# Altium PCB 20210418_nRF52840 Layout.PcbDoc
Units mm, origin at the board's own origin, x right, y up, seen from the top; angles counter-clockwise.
Board outline 17.42 x 19.45 mm, 4 copper layers (Top Layer, L2_GND, Layer 3, Bottom Layer), stack 1.51 mm thick; 44 components, 56 nets, 250 pads, 364 vias.
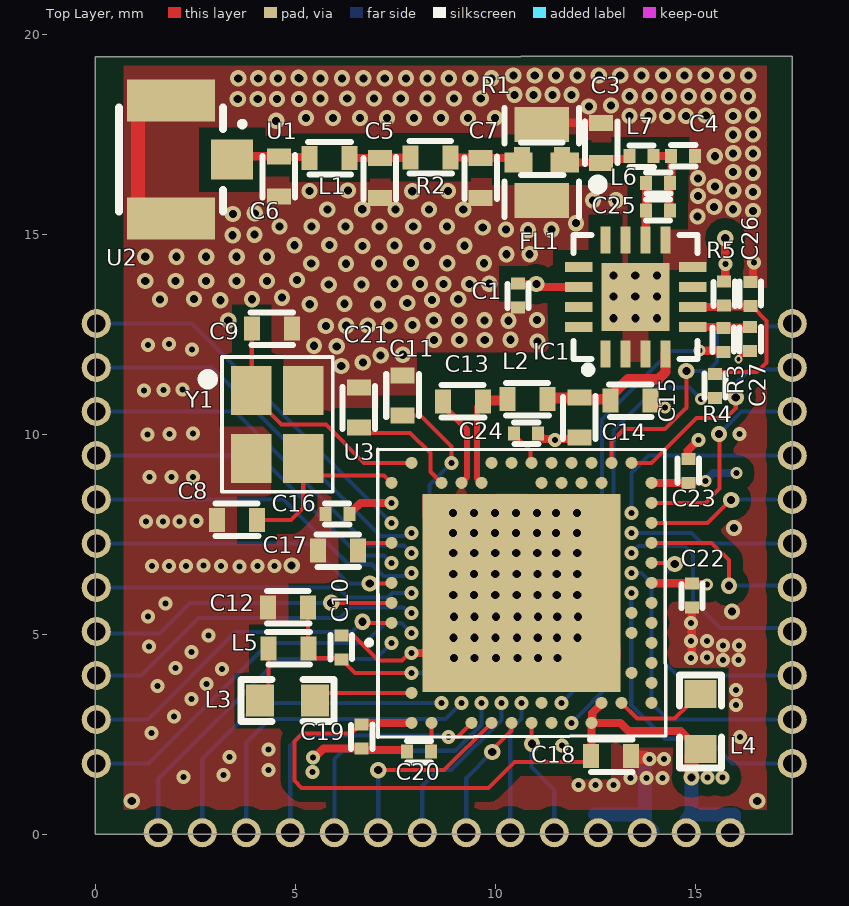
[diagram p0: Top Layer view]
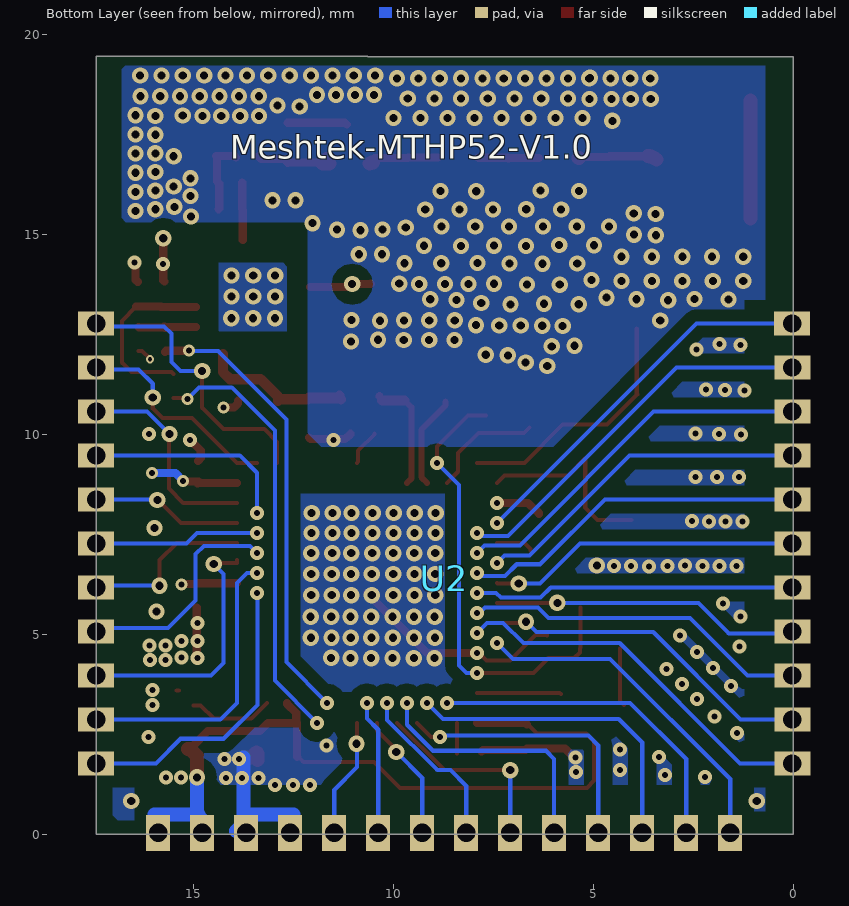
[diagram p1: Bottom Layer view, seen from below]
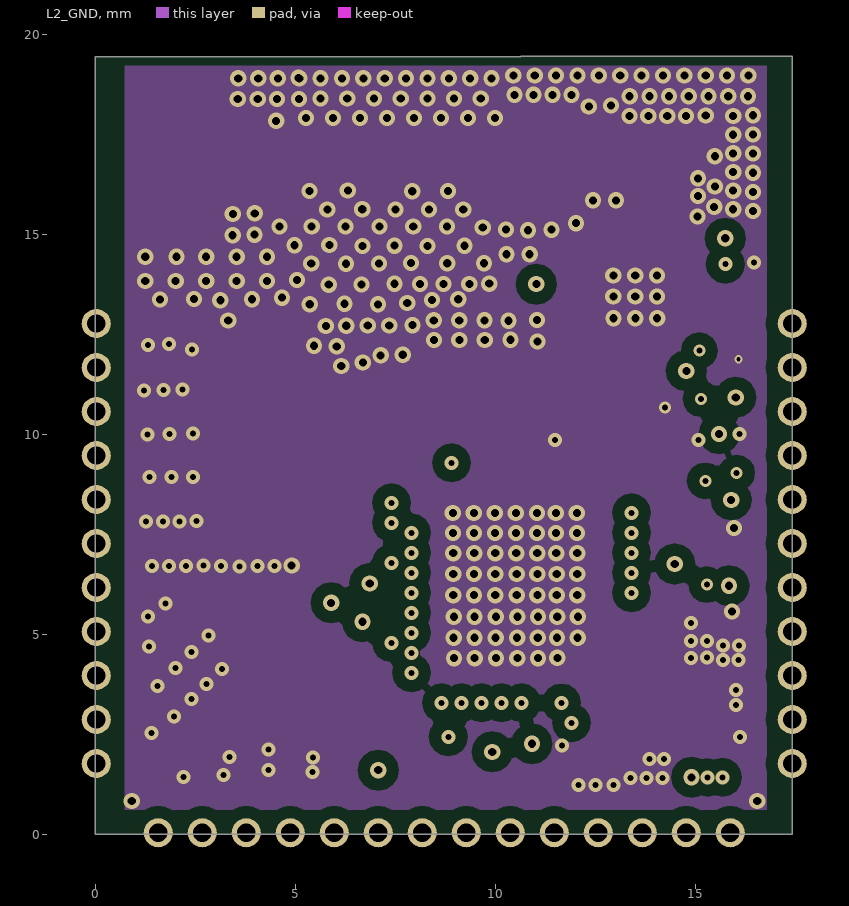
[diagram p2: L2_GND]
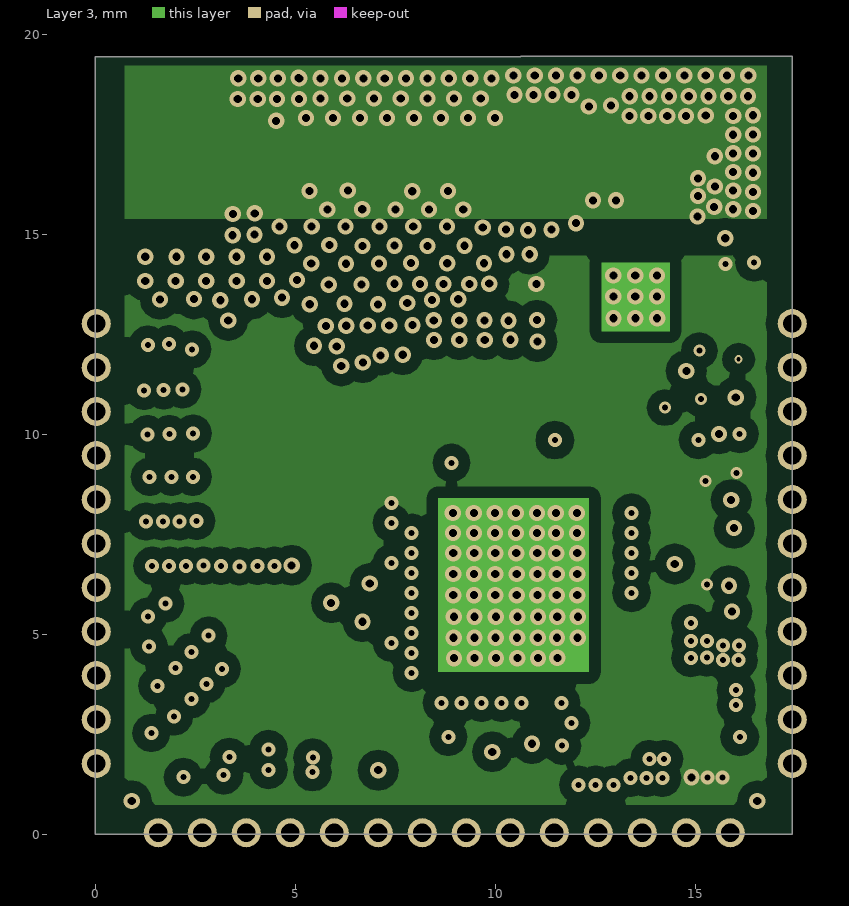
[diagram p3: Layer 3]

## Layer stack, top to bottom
Top Solder: solder mask 0.0102, Solder Resist, Dk 3.5
Top Layer: signal copper 0.0178
Dielectric 1: core 0.286, FR-4, Dk 4.5
L2_GND: signal copper 0.036
Dielectric 2: core 0.83, FR-4, Dk 4.5
Layer 3: signal copper 0.036
Dielectric 3: core 0.286, FR-4, Dk 4.5
Bottom Layer: signal copper 0.0178
Bottom Solder: solder mask 0.0102, Solder Resist, Dk 3.5

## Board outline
10.626,19.44 10.631,19.435 10.645,19.449 17.424,19.449 17.424,0 0,0 0,19.44

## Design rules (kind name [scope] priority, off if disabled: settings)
Clearance [All] p1: gap=0.1 ignorepadtopadclearanceinfootprint=FALSE except(0.3: Arc-Poly Arc-Region Track-Poly Track-Region SMDPad-Poly SMDPad-Region THPad-Poly THPad-Region Via-Poly Via-Region Fill-Poly Fill-Region Poly-Region Poly-Text Poly-Hole Region-Region Region-Text Region-Hole)
PlaneClearance [All] p1: clearance=0.3
PlaneConnect [All] p1: planeconnectstyle=Direct reliefexpansion=0.508 reliefentries=4 reliefconductorwidth=0.254 reliefairgap=0.254
PolygonConnect [All] p1: connectstyle=Direct reliefconductorwidth=0.254 reliefentries=4 polygonreliefangle="90 Angle" airgapwidth=0.254
RoutingVias [All] p1: holewidth=0.203 width=0.406 viastyle="Through Hole" minholewidth=0.203 minwidth=0.406 maxholewidth=0.203 maxwidth=0.406
SolderMaskExpansion [All] p1: expansion=0.102
Width [All] p1: maxlimit=0.35 minlimit=0.102 preferedwidth=0.203
28 further rules are at their usual default settings.

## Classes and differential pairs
component class "20210418_Controller Section": C8 C9 C10 C11 C12 C13 C14 C15 C16 C17 C18 C19 C20 C21 C22 C23 C24 L2 L3 L4 L5 U2 U3 Y1
component class "Antenna Section": C1 C3 C4 C5 C6 C7 C25 C26 C27 FL1 IC1 L1 L6 L7 R1 R2 R3 R4 R5 U1

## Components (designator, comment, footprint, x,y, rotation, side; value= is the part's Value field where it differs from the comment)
C1 "1uF" C0201 10.59,13.46 r90 top
C3 "DNP" C0402 12.653,17.324 r90 top
C4 "1.3pF" C0201 14.698,16.983 r180 top
C5 "1.2pF" C0402 7.104,16.361 r270 top
C6 "1.2pF" C0402 4.575,16.409 r270 top
C7 "DNP" C0402 9.62,16.367 r270 top
C8 "12pF" C0402 3.5,7.868 r180 top
C9 "12pF" C0402 4.449,12.631 r0 top
C10 "1uF" C0201 6.119,4.673 r270 top
C11 "DNP" C0402 7.689,11.009 r90 top
C12 "47nF" C0402 4.781,5.682 r180 top
C13 "0.8pF" C0402 9.148,10.829 r180 top
C14 "0.5pF" C0402 12.089,10.375 r270 top
C15 "DNP" C0402 13.415,10.823 r0 top
C16 "100nF" C0201 6.048,7.979 r0 top
C17 "DNP" C0402 6.105,7.078 r0 top
C18 "4.7uF" C0402 12.935,1.945 r0 top
C19 "1uF" C0201 6.681,2.441 r90 top
C20 "100nF" C0201 8.091,2.04 r0 top
C21 "100pF" C0402 6.58,10.627 r270 top
C22 "100nF" C0201 14.94,5.963 r90 top
C23 "100nF" C0201 14.801,9.083 r270 top
C24 "820pF" C0201 10.77,10.048 r180 top
C25 "0.7pF" C0201 14.066,15.628 r180 top
C26 "DNP" C0201 16.347,13.512 r270 top
C27 "DNP" C0201 16.399,12.378 r90 top
FL1 "LFB212G45CG1B982" FILT-BPF4_2X1P25 11.159,16.794 r270 top
IC1 "RFX2401C" QFN16_0P5_3X3_EP_0P6 13.505,13.43 r90 top
L1 "8.2nH" L0402 5.876,16.908 r0 top
L2 "4.7nH" L0402 10.784,10.874 r180 top
L3 "10uH" L0603 4.786,3.307 r180 top
L4 "10uH" L0603 15.097,2.838 r90 top
L5 "15nH" L0402 4.851,4.649 r0 top
L6 "1.2nH" L0201 14.056,16.277 r180 top
L7 "0.7nH" L0201 13.669,16.951 r0 top
R1 "DNP" R0402 11.185,16.898 r180 top
R2 "0E" R0402 8.392,16.938 r180 top
R3 "1K" R0201#1 15.775,12.442 r270 top
R4 "1K" R0201#1 15.565,11.294 r270 top
R5 "10K, DNP" R0201#2 15.775,13.431 r90 top
U1 "Component_1" "UFL Conn" 2.022,16.865 r90 top
U2 "nRF52840 Module" "nRF52840 Module" 9.764,13.875 r0 top locked
U3 "nRF52840" nRF52840 10.781,4.637 r90 top
Y1 "XRCGB32M000FXH2CR0" XTAL4_1P3_2P5X2_0P55 4.548,10.245 r270 top

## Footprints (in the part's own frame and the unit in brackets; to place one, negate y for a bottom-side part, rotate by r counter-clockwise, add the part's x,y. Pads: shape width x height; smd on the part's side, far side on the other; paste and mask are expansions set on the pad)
C0201 [mm] "C0201, CAP"
  rect 0.3x0.35 smd mask+0.051: 1(0.302,0.03) 2(-0.298,0.03)
  silkscreen extent -0.31,-0.24 0.3,0.29, body extent -0.3,-0.12 0.3,0.18, height 0.5
C0402 [mm] "C0402"
  rect 0.4x0.6 smd mask+0.051: 1(-0.539,0.013) 2(0.461,0.013)
  silkscreen extent -0.57,-0.4 0.49,0.42, body extent -0.56,-0.26 0.49,0.29, height 1
FILT-BPF4_2X1P25 [mil] "FILT-BPF4_2X1P25"
  rect 20x27.99 smd mask+2: 1(0.06,22.87) 3(0.06,-22.87)
  rect 34.02x54.02 smd mask+2: 2(37.46,0) 4(-37.34,0)
  silkscreen extent -54,-37 54,37, body extent -42,-27 42,27, height 0
L0201 [mm] "L0201, INDUCTOR"
  rect 0.3x0.35 smd mask+0.051: 1(0.29,0.001) 2(-0.31,0.001)
  silkscreen extent -0.32,-0.27 0.29,0.26, body extent -0.31,-0.15 0.29,0.15, height 0.5
L0402 [mm] "L0402, INDUCTOR"
  rect 0.4x0.6 smd mask+0.051: 1(-0.518,-0.002) 2(0.482,-0.002)
  silkscreen extent -0.55,-0.41 0.51,0.4, body extent -0.54,-0.28 0.51,0.27, height 1
L0603 [mm] "L0603_INDUCTOR"
  rect 0.7x0.8 smd mask+0.051: 1(-0.708,-0.033) 2(0.667,-0.033)
  silkscreen extent -1.18,-0.56 1.14,0.49
nRF52840 [mm] "nRF52840_SOC_Footprint"
  round 0.3 smd: A8(0.147,3.377) A10(0.647,3.377) A12(1.147,3.377) A14(1.647,3.377) A16(2.147,3.377) A18(2.647,3.377) A20(3.147,3.377) A22(3.647,3.377) A23(4.147,3.377) AA24(4.647,-2.123) AB2(-1.353,-2.373) AC5(-0.603,-2.623) AC9(0.397,-2.623) AC11(0.897,-2.623) AC13(1.397,-2.623) AC15(1.897,-2.623) AC17(2.397,-2.623) AC19(2.897,-2.623) AC21(3.397,-2.623) AC24(4.647,-2.623) AD2(-1.353,-3.123) AD4(-0.853,-3.123) AD6(-0.353,-3.123) AD8(0.147,-3.123) AD10(0.647,-3.123) AD12(1.147,-3.123) AD14(1.647,-3.123) AD16(2.147,-3.123) AD18(2.647,-3.123) AD20(3.147,-3.123) AD22(3.647,-3.123) AD23(4.147,-3.123) B1(-1.853,2.877) B3(-1.103,2.877) B5(-0.603,2.877) B7(-0.103,2.877) B9(0.397,2.877) B11(0.897,2.877) B13(1.397,2.877) B15(1.897,2.877) B17(2.397,2.877) B19(2.897,2.877) B24(4.647,2.877) C1(-1.853,2.377) D2(-1.353,2.127) D23(4.147,2.127) E24(4.647,1.877) F2(-1.353,1.627) F23(4.147,1.627) G1(-1.853,1.377) H2(-1.353,1.127) H23(4.147,1.127) J1(-1.853,0.877) J24(4.647,0.877) K2(-1.353,0.627) L1(-1.853,0.377) L24(4.647,0.377) M2(-1.353,0.127) N1(-1.853,-0.123) N24(4.647,-0.123) P2(-1.353,-0.373) P23(4.147,-0.373) R1(-1.853,-0.623) R24(4.647,-0.623) T2(-1.353,-0.873) T23(4.147,-0.873) U1(-1.853,-1.123) U24(4.647,-1.123) V23(4.147,-1.373) W1(-1.853,-1.623) W24(4.647,-1.623) Y2(-1.353,-1.873) Y23(4.147,-1.873)
  rect 4.95x4.95 smd: DP1(1.397,0.127)
  silkscreen extent -2.21,-3.48 4.99,3.96
"nRF52840 Module" [mil] "nRF52840 Module_PCB"
  round 28.62 / inner round 28.62 / far side rect 0x0 hole 18 mask+2: 1(-383.5,-43.66) 2(-383.5,-86.97) 3(-383.5,-130.27) 4(-383.5,-173.58) 5(-383.5,-216.89) 6(-383.5,-260.19) 7(-383.5,-303.5) 8(-383.5,-346.81) 9(-383.5,-390.12) 10(-383.5,-433.42) 11(-383.5,-476.73) 13(-279.19,-544.84) 14(-235.88,-544.84) 15(-192.57,-544.84) 16(-149.27,-544.84) 17(-105.96,-544.84) 18(-62.65,-544.84) 19(-19.35,-544.84) 20(23.96,-544.84) 21(67.27,-544.84) 22(110.57,-544.84) 23(153.88,-544.84) 24(197.19,-544.84) 25(240.5,-544.84) 26(301.5,-476.72) 27(301.5,-433.41) 28(301.5,-390.11) 29(301.5,-346.8) 30(301.5,-303.49) 31(301.5,-260.18) 32(301.5,-216.88) 33(301.5,-173.57) 34(301.5,-130.26) 35(301.5,-86.96) 36(301.5,-43.65)
  round 28.62 / inner round 28.62 / far side round 0 hole 18 mask+2: 12(-322.5,-544.84)
  rect 35.44x23.62 smd far side paste+0 mask+2: ""(-383.54,-476.73) ""(-383.54,-433.43) ""(-383.54,-390.12) ""(-383.54,-346.81) ""(-383.54,-303.51) ""(-383.54,-260.2) ""(-383.54,-216.89) ""(-383.54,-173.58) ""(-383.54,-130.28) ""(-383.54,-86.97) ""(-383.52,-43.66) ""(301.52,-476.73) ""(301.52,-433.43) ""(301.52,-390.12) ""(301.52,-346.81) ""(301.52,-303.5) ""(301.52,-260.2) ""(301.52,-216.89) ""(301.52,-173.58) ""(301.52,-130.28) ""(301.52,-86.97) ""(301.52,-43.66)
  rect 23.62x35.44 smd far side paste+0 mask+2: ""(-322.49,-544.85) ""(-279.19,-544.85) ""(-235.88,-544.85) ""(-192.57,-544.85) ""(-149.26,-544.85) ""(-105.96,-544.85) ""(-62.65,-544.85) ""(-19.34,-544.85) ""(23.96,-544.85) ""(67.27,-544.85) ""(110.58,-544.85) ""(153.88,-544.84) ""(197.18,-544.84) ""(240.49,-544.84)
  body extent -383,-545 301,258, height 0
QFN16_0P5_3X3_EP_0P6 [mil] "QFN16_0P5_3X3_EP_0P6"
  rect 27x10 smd mask+2: 1(-56.1,29.53) 2(-56.1,9.84) 3(-56.1,-9.84) 4(-56.1,-29.53) 9(56.1,-29.53) 10(56.1,-9.84) 11(56.1,9.84) 12(56.1,29.53)
  rect 10x27 smd mask+2: 5(-29.53,-56.1) 6(-9.84,-56.1) 7(9.84,-56.1) 8(29.53,-56.1) 13(29.53,56.1) 14(9.84,56.1) 15(-9.84,56.1) 16(-29.53,56.1)
  rect 67.01x67.01 smd paste-33.5 mask+2: 17(0,0)
  silkscreen extent -61,-61 61,61, body extent -61,-61 61,61, height 0
R0201#1 [mm] "0201, Res"
  rect 0.3x0.35 smd mask+0.051: 1(0.385,-0.07) 2(-0.215,-0.07)
  silkscreen extent -0.22,-0.34 0.39,0.19, body extent -0.21,-0.22 0.38,0.08, height 0.5
R0201#2 [mm] "0201, Res"
  rect 0.3x0.35 smd mask+0.051: 1(0.385,0.057) 2(-0.215,0.057)
  silkscreen extent -0.22,-0.22 0.39,0.32, body extent -0.21,-0.09 0.38,0.21, height 0.5
R0402 [mm]
  rect 0.4x0.6 smd mask+0.051: 1(-0.487,0.018) 2(0.513,0.018)
  silkscreen extent -0.52,-0.39 0.54,0.42, body extent -0.51,-0.26 0.54,0.29, height 1
"UFL Conn" [mm] "UFL Connector"
  rect 1x1.05 smd: 1(0,-1.398)
  rect 1.05x2.2 smd: 2(-1.475,0.127) 3(1.475,0.127)
  silkscreen extent -1.3,-1.68 1.3,1.43
XTAL4_1P3_2P5X2_0P55 [mm] "XTAL4_1P3_2P5X2_0P55"
  rect 1.219x1.016 smd mask+0.051: 1(-0.85,-0.65) 2(0.85,-0.65) 3(0.85,0.65) 4(-0.85,0.65)
  silkscreen extent -1.68,-1.86 1.68,1.38, body extent -1.3,-1.05 1.3,1.05, height 0

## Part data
C1 C4 C10 C16 C19 C20 C22 C23 C24 C25 C26 C27: library part C0201, "C0201, CAP"
C3 C5 C7 C8 C9 C11 C13 C17 C18 C21: library part C0402, "C0402"
C6: library part C0402, "1.2pFC0402"
C12: library part C0402, "Capacitor, X7R, ±10 %"
C14 C15: library part C0402, "Capacitor, NP0, ±10 %, 0402"
FL1: library part LFB212G45CG1C187, "Filter", Manufacturer_Name="Murata Electronics", Mouser Part Number=81-LFB212G45CG1C187
IC1: "Integrated Circuit", Manufacturer_Name=Skyworks, Mouser Part Number=477-RFX2401C
L1: library part L0402, "8.2nH, 0402"
L2: library part L0402, "High frequency chip inductor ±5 %"
L3 L4: library part L0603, "L0603, INDUCTOR"
L5: library part L0402
L6 L7: library part L0201, "L0201, INDUCTOR"
R1: library part R0402
R2: library part R0402, "0402"
R3 R4 R5: library part R0201, "R0201"
U2: "nRF52840 Module_Symbole"
U3: "nRF52840 SOC"
Y1: "Crystal or Oscillator", Manufacturer_Name="Murata Electronics", Mouser Part Number=81-XRCGB32M000FXH2CR

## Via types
v1: diameter 0.406, hole 0.203, Top Layer to Bottom Layer, tented both sides, 260 vias
v2: diameter 0.35, hole 0.15, Top Layer to Bottom Layer, tented both sides, 97 vias
v3: diameter 0.3, hole 0.15, Top Layer to Bottom Layer, tented both sides, 6 vias
v4: diameter 0.204, hole 0.102, Top Layer to Bottom Layer, tented both sides, 1 vias

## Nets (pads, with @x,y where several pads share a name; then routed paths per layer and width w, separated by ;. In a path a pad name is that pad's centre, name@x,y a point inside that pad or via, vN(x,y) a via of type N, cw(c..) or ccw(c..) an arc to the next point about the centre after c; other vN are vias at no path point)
ANT: C13.1 L2.2 U3.H23 | length 2.8
  Top Layer w0.15: U3.H23 9.547,8.891 9.547,10.676 C13.1
  Top Layer w0.203: C13.1 C13.1@9.717,10.846 ; L2.2@10.272,10.846 L2.2 ; L2.2@10.339,10.94 L2.2@10.339,10.96
  Top Layer w0.254: C13.1@9.717,10.846 L2.2@10.272,10.846
BT_TXRX: C14.1 C15.1 IC1.4 L2.1 | length 4.6
  Top Layer w0.254: L2.1 11.321,10.895 12.083,10.895 C14.1 ; L2.1@11.339,10.96 11.339,10.956 11.381,10.914 C14.1 ; C15.1 C15.1@12.876,10.864 ; IC1.4 14.255,11.552 14.076,11.373 13.313,11.373 12.876,10.936 C15.1@12.876,10.864 ; C14.1 12.141,10.875 12.837,10.875 12.851,10.889 C15.1@12.876,10.864
DCC: L3.1 U3.B3 | length 2.1
  Top Layer w0.102: L3.1@5.804,3.501 5.836,3.534 U3.B3
DEC1: C20.1 U3.C1 | length 0.8
  Top Layer w0.102: C20.1@8.399,2.018 8.401,2.02 8.401,2.781 U3.C1
DEC2: C17.2 U3.A18 | length 0.9
  Top Layer w0.102: C17.2 6.566,7.135 6.715,7.284 U3.A18
DEC3: C21.2 U3.D23 | length 2.9
  Top Layer w0.102: C21.2 6.727,10.032 7.87,10.032 8.377,9.525 8.377,9.061 U3.D23
DEC4_6: C10.1 C11.1 C12.1 L5.2 U3.B5 U3.E24 | length 11.7
  Top Layer w0.102: C12.1 5.32,4.661 L5.2 5.333,4.547 5.482,4.398 6.122,4.398 C10.1 6.486,4.034 v2(7.904,4.034) ; C11.1 8.13,10.47 8.904,9.696 v2(8.904,9.284)
  Bottom Layer w0.102: v2(7.904,4.034) 8.166,4.034 8.348,4.216 8.348,8.728 v2(8.904,9.284)
DEC5: C24.1 U3.N24 | length 0.9
  Top Layer w0.102: C24.1 10.468,9.993 10.874,9.587 10.874,9.314 U3.N24
GND: C1.2 C3.2 C4.2 C5.2 C6.2 C7.2 C8.2 C9.2 C11.2 C12.2 C13.2 C14.2 C15.2 C16.2 C17.1 C18.2 C19.2 C20.2 C21.1 C22.2 C23.2 C24.2 C26.2 C27.2 FL1.2 FL1.4 IC1.2 IC1.3 IC1.8 IC1.9 IC1.11 IC1.17 U1.2 U1.3 U2.22 U2.23 U3.B7 U3.DP1 U3.F23 Y1.2 Y1.4 | length 23.3
  Top Layer w0.102: 6.149,4.971 6.157,4.979 6.443,4.979 7.076,4.346 7.664,4.346 7.852,4.534 U3.B7 ; v4(16.082,11.873) 16.082,11.888 16.274,12.08 C27.2
  Top Layer w0.15: C13.2 8.687,10.723 9.297,10.112 9.297,8.927 U3.F23
  Top Layer w0.203: v2(5.435,1.916) 5.475,1.916 5.699,2.141 6.649,2.141 C19.2 6.688,2.106 7.756,2.106 C20.2 ; U3.B7 9.154,4.534 U3.DP1 ; C24.2 11.068,9.993 11.117,9.945 11.142,9.945 11.206,9.88 11.46,9.88 v2(11.488,9.852) 11.516,9.88 12.069,9.88 C14.2 ; FL1.4 11.201,17.785 C3.2 ; C15.2 13.876,10.764 13.975,10.666 v3@14.24,10.666 ; C23.2@14.879,9.333 C23.2 14.811,9.401 14.811,9.591 v2(15.075,9.855) ; v2@14.91,4.404 C22.2 ; C26.2 16.392,13.81 16.441,13.859 16.441,14.264 v2(16.469,14.292)
  Top Layer w0.35: U1.2@1.068,15.39 U1.3@1.068,18.34 ; C18.2@13.396,1.858 C18.2 13.396,2.023 13.421,2.048 13.556,1.914 v2@13.745,1.914
  Bottom Layer w0.15: 12.493,0.498 12.493,0.115 U2.22
  Bottom Layer w0.35: 12.493,0.498 13.594,0.498 ; v2@13.745,1.914 13.745,0.273 13.934,0.084
  other v1: 0.909,0.833 16.548,0.831 8.963,4.401 9.482,4.401 10.013,4.401 10.55,4.401 11.064,4.401 11.549,4.409 8.958,4.911 9.477,4.911 10.008,4.911 10.545,4.911 11.059,4.911 11.544,4.911 12.058,4.911 8.962,5.437 9.481,5.437 10.012,5.437 10.549,5.437 11.063,5.437 11.548,5.437 12.062,5.437 15.915,5.568 8.948,5.976 9.467,5.976 9.998,5.976 10.535,5.976 11.049,5.976 11.534,5.976 12.048,5.976 8.948,6.505 9.467,6.505 9.998,6.505 10.535,6.505 11.049,6.505 11.534,6.505 12.048,6.505 4.908,6.72 8.947,7.026 9.472,7.026 9.998,7.026 10.523,7.026 11.048,7.026 11.522,7.026 12.047,7.026 8.94,7.533 9.465,7.533 9.991,7.533 10.516,7.533 11.041,7.533 11.515,7.533 12.04,7.533 15.968,7.652 8.937,8.033 9.462,8.033 9.988,8.033 10.513,8.033 11.038,8.033 11.512,8.033 12.037,8.033 6.146,11.705 6.687,11.79 7.133,11.971 7.685,11.987 5.467,12.21 6.036,12.196 11.051,12.315 8.465,12.358 9.1,12.358 9.735,12.358 10.381,12.362 5.762,12.705 6.273,12.71 6.811,12.715 7.348,12.715 7.928,12.726 3.321,12.842 10.326,12.836 8.461,12.846 9.096,12.846 9.731,12.846 11.041,12.854 12.953,12.898 13.499,12.898 14.045,12.898 5.359,13.249 7.068,13.246 6.228,13.262 7.797,13.278 3.124,13.35 8.416,13.352 8.416,13.352 1.614,13.369 3.918,13.373 9.072,13.374 9.072,13.374 2.466,13.379 4.668,13.413 12.95,13.443 13.496,13.443 14.042,13.443 5.836,13.739 6.651,13.741 8.117,13.753 8.704,13.753 9.35,13.758 7.48,13.761 9.846,13.763 1.246,13.833 2.008,13.833 2.77,13.833 3.532,13.833 4.294,13.833 5.038,13.852 12.95,13.965 13.496,13.965 14.042,13.965 5.398,14.265 6.265,14.26 7.092,14.266 7.892,14.279 8.796,14.273 9.713,14.273 1.246,14.437 2.028,14.437 2.77,14.437 3.532,14.437 4.294,14.437 10.278,14.5 10.857,14.5 4.979,14.723 6.679,14.706 7.481,14.713 8.305,14.706 9.226,14.712 5.849,14.728 3.432,14.973 3.981,14.989 10.816,15.1 10.264,15.12 11.402,15.114 9.685,15.168 4.606,15.192 5.408,15.19 6.254,15.19 7.101,15.19 7.947,15.19 8.794,15.19 12.013,15.276 15.055,15.443 3.437,15.506 3.986,15.522 16.442,15.578 5.799,15.616 6.672,15.632 6.672,15.616 7.501,15.616 8.339,15.616 9.197,15.616 15.945,15.623 15.47,15.684 12.442,15.846 13.019,15.846 15.066,15.954 16.442,16.057 5.353,16.081 6.312,16.092 7.922,16.074 8.813,16.083 15.945,16.089 15.487,16.19 15.066,16.397 16.442,16.536 15.945,16.555 15.487,16.948 15.945,17.021 16.442,17.015 15.945,17.487 16.442,17.494 4.52,17.834 5.264,17.904 5.939,17.904 6.614,17.904 7.289,17.904 7.963,17.904 8.638,17.904 9.313,17.904 9.988,17.904 13.352,17.958 13.824,17.958 14.297,17.958 14.769,17.958 15.26,17.969 15.945,17.953 16.442,17.973 12.337,18.193 12.889,18.215 3.561,18.381 4.059,18.381 4.539,18.381 5.089,18.381 5.631,18.391 6.298,18.391 6.966,18.391 7.633,18.391 8.301,18.391 8.968,18.391 9.636,18.391 13.358,18.449 13.851,18.449 14.343,18.449 14.836,18.449 15.329,18.449 15.821,18.449 16.314,18.449 10.478,18.484 10.953,18.484 11.429,18.484 11.904,18.484 3.571,18.897 4.072,18.897 4.562,18.897 5.078,18.909 5.096,18.897 5.631,18.897 6.165,18.897 6.699,18.897 7.233,18.897 7.768,18.897 8.302,18.897 8.836,18.897 9.371,18.897 9.905,18.897 16.324,18.966 10.45,18.967 10.984,18.967 11.519,18.967 12.053,18.967 12.587,18.967 13.122,18.967 13.656,18.967 14.19,18.967 14.724,18.967 15.259,18.967 15.793,18.967
  other v2: 12.073,1.236 12.509,1.235 12.948,1.235 13.372,1.41 13.775,1.407 14.176,1.407 2.199,1.424 3.209,1.475 5.427,1.552 4.328,1.61 13.85,1.882 14.221,1.882 3.349,1.925 4.328,2.122 11.671,2.213 16.111,2.431 1.4,2.528 1.969,2.943 16.02,3.236 2.4,3.374 16.016,3.601 1.548,3.71 2.779,3.752 3.168,4.131 2,4.152 15.693,4.351 16.075,4.351 14.885,4.404 15.285,4.417 7.901,4.527 2.4,4.552 1.341,4.69 15.693,4.713 16.091,4.713 14.885,4.829 15.288,4.833 2.831,4.962 14.885,5.28 1.321,5.443 1.756,5.767 3.602,6.696 1.422,6.711 1.845,6.711 2.269,6.711 2.702,6.714 3.138,6.711 4.054,6.705 4.477,6.711 1.685,7.815 1.267,7.819 2.104,7.821 2.53,7.831 1.358,8.935 1.904,8.935 2.435,8.935 1.305,9.996 1.851,10.004 2.442,10.019 16.106,10.008 1.218,11.089 1.708,11.101 2.177,11.122 2.42,12.12 1.312,12.234 1.843,12.249
  other v3: 14.241,10.665
NetC3_1: C3.1 FL1.1 L7.2 R1.1 | length 2
  Top Layer w0.203: FL1.1 11.744,16.789 12.636,16.789 C3.1@12.638,16.787 ; C3.1 C3.1@12.638,16.787 ; L7.2 13.359,16.927 13.31,16.878 12.73,16.878 C3.1@12.638,16.787
  Top Layer w0.35: FL1.1@11.587,16.763 FL1.1@11.767,16.763 ; R1.1 11.672,16.789 FL1.1@11.697,16.764 ; FL1.1@11.767,16.781 11.774,16.788 FL1.1@11.776,16.785
NetC4_1: C4.1 C25.2 L6.2 L7.1 | length 1.9
  Top Layer w0.203: L7.1@13.926,16.919 L7.1 C4.1@14.395,16.953 ; C25.2@14.364,15.622 14.348,15.638 14.348,16.264 14.404,16.32 C4.1@14.404,16.913 ; C4.1@14.389,16.898 C4.1@14.404,16.913 ; C4.1@14.427,16.956 14.404,16.933 C4.1@14.404,16.913
NetC5_1: C5.1 L1.2 R2.2 | length 1.5
  Top Layer w0.203: L1.2 6.362,16.903 7.114,16.903 C5.1 7.127,16.91 7.869,16.91 R2.2
NetC6_1: C6.1 L1.1 U1.1 | length 2.2
  Top Layer w0.203: U1.1 3.503,16.948 3.591,16.948 C6.1 4.609,16.927 5.337,16.927 5.355,16.909 L1.1
  Top Layer w0.35: U1.1 cw(c3.625,16.66) 3.591,16.948 cw(c3.625,16.66) U1.1@3.625,16.95 ; L1.1@5.355,16.909 L1.1@5.369,16.909
NetC7_1: C7.1 FL1.3 R1.2 R2.1 | length 1.7
  Top Layer w0.203: R2.1 8.886,16.913 9.626,16.913 C7.1 FL1.3@10.465,16.906
  Top Layer w0.35: FL1.3@10.502,16.798 cw(c10.502,16.678) FL1.3@10.587,16.763
NetC25_1: C25.1 IC1.10 L6.1 | length 2.1
  Top Layer w0.203: IC1.10 13.76,14.86 13.76,15.594 C25.1 C25.1 C25.1@13.765,15.623 ; L6.1 13.765,16.275 C25.1@13.765,15.623 ; L6.1@13.78,16.296 13.772,16.288 13.772,15.63 C25.1@13.765,15.623
NetC26_1: C26.1 IC1.6 R4.2 R5.2 | length 4.5
  Top Layer w0.102: R4.2 15.538,11.553 16.543,11.553 16.777,11.787 16.777,12.835 16.424,13.188 16.402,13.21 C26.1
  Top Layer w0.203: IC1.6 15.784,13.18 ccw(c15.784,13.214) 15.807,13.19 15.809,13.188 C26.1@16.424,13.188
NetC27_1: C27.1 IC1.5 R3.2 | length 1.5
  Top Layer w0.203: IC1.5 15.686,12.68 ccw(c15.686,12.739) R3.2@15.728,12.697 ; R3.2 15.716,12.668 16.358,12.668 C27.1
NetL3_2: L3.2 L5.1 | length 1.5
  Top Layer w0.102: L3.2@4.233,3.229 4.333,3.33 L5.1
NetL4_2: L4.2 U3.AB2 | length 2.2
  Top Layer w0.102: U3.AB2 13.547,2.891 14.484,2.891 14.815,3.222 L4.2@14.991,3.222 ; L4.2@15.359,3.59 L4.2@15.409,3.59
P0.00/XL1: U2.13 U3.D2 | length 8.4
  Bottom Layer w0.102: U2.13 2.673,1.882 4.075,3.284 v2(8.654,3.284)
P0.01/XL2: U2.14 U3.F2 | length 8.1
  Bottom Layer w0.102: U2.14 3.773,2.296 4.36,2.883 8.753,2.883 v2(9.154,3.284)
P0.02/AIN0: U2.8 U3.A12 | length 7.7
  Top Layer w0.102: v1(5.895,5.784) U3.A12
  Bottom Layer w0.102: U2.8 0.066,5.022 1.609,5.022 2.371,5.784 v1(5.895,5.784)
P0.03/AIN1: U2.7 U3.B13 | length 8
  Bottom Layer w0.102: U2.7 6.06,6.166 6.312,5.914 7.306,5.914 7.426,6.034 v2(7.904,6.034)
P0.04/AIN2: U2.17 U3.J1 | length 4.9
  Top Layer w0.102: v1(7.073,1.601) 8.721,1.601 U3.J1
  Bottom Layer w0.102: U2.17 v1(7.073,1.601)
P0.05/AIN3: U2.18 U3.K2 | length 4.3
  Bottom Layer w0.102: U2.18 8.173,1.21 8.564,1.601 8.897,1.601 10.154,2.858 v2(10.154,3.284)
P0.06: U2.19 U3.L1 | length 3.2
  Top Layer w0.102: v1(9.921,2.057) 9.921,2.104 10.404,2.587 U3.L1
  Bottom Layer w0.102: 9.273,0.036 9.273,1.408 v1(9.921,2.057)
P0.07: U2.20 U3.M2 | length 3.4
  Bottom Layer w0.102: U2.20 10.373,2.612 10.654,2.893 v2(10.654,3.284)
P0.08: U2.21 U3.N1 | length 3
  Top Layer w0.102: U3.N1 10.904,2.271 v1(10.913,2.262)
  Bottom Layer w0.102: v1(10.913,2.262) 10.913,2.256 10.902,2.245 10.902,1.678 11.473,1.107 U2.21
P0.18/RESET/QSPI_CSN: U2.26 U2.@17.423,1.766 U3.AC13 | length 7.4
  Bottom Layer w0.102: v2(13.404,6.034) 13.396,6.026 13.396,3.235 14.245,2.386 15.312,2.386 15.932,1.766 U2.26
P0.19/QSPI/SCK: U2.27 U3.AC15 | length 7.3
  Bottom Layer w0.102: v2(13.404,6.534) 13.654,6.534 13.904,6.284 13.904,3.284 14.322,2.866 U2.27
P0.20: U2.28 U2.@17.423,3.966 U3.AD16 | length 6.6
  Top Layer w0.102: U3.AD16@13.904,6.854 U3.AD16 13.905,6.783 14.457,6.783 v1(14.485,6.755)
  Bottom Layer w0.102: v1(14.485,6.755) 14.237,6.507 14.237,4.284 14.555,3.966 U2.28
P0.21/QSPI: U2.29 U2.@17.423,5.066 U3.AC17 | length 5.7
  Bottom Layer w0.102: v2(13.404,7.034) 13.58,7.21 14.731,7.21 14.94,7.001 14.94,5.841 15.63,5.151 17.215,5.151 17.276,5.212 U2.29
P0.22/QSPI: U2.30 U3.AD18 | length 4.4
  Top Layer w0.102: U3.AD18 15.409,7.284 15.841,6.852 v1(15.841,6.213)
  Bottom Layer w0.102: v1(15.841,6.213) 17.371,6.213 17.42,6.164 U2.30 17.421,6.168
P0.23/QSPI: U2.31 U2.@17.423,7.266 U3.AC19 | length 4.1
  Bottom Layer w0.102: v2(13.404,7.534) 14.901,7.534 15.169,7.266 U2.31
P0.24: U2.32 U3.AD20 | length 3.8
  Top Layer w0.102: U3.AD20 15.304,7.784 15.901,8.381 15.901,8.363 v1(15.895,8.357)
  Bottom Layer w0.102: v1(15.895,8.357) 15.904,8.366 U2.32
P0.25: U2.33 U3.AC21 | length 5.2
  Bottom Layer w0.102: v2(13.404,8.034) 13.404,9.036 13.834,9.466 U2.33
P0.26: U2.15 U3.G1 | length 7
  Top Layer w0.102: v2(8.825,2.433) 9.053,2.433 U3.G1
  Bottom Layer w0.102: U2.15 4.873,2.221 5.117,2.465 v2@8.882,2.465
P0.27: U2.16 U3.H2 | length 6.4
  Bottom Layer w0.102: U2.16 5.974,0.038 5.974,1.884 6.176,2.086 9.004,2.086 9.654,2.736 v2(9.654,3.284)
P0.28/AIN4: U2.9 U3.B11 | length 8.6
  Bottom Layer w0.102: U2.9 1.145,3.966 2.582,5.403 6.12,5.403 6.382,5.665 7.706,5.665 7.837,5.534 v2(7.904,5.534)
P0.29/AIN5: U2.10 U3.A10 | length 8.4
  Top Layer w0.102: v1(6.678,5.311) 6.705,5.284 U3.A10
  Bottom Layer w0.102: U2.10 0.026,2.869 1.316,2.869 3.498,5.051 6.418,5.051 v1(6.678,5.311)
P0.30/AIN6: U2.11 U3.B9 | length 9.4
  Bottom Layer w0.102: U2.11 1.324,1.766 4.335,4.777 6.745,4.777 7.252,5.284 7.654,5.284 v2(7.904,5.034)
P0.31/AIN7: U2.12 U3.A8 | length 8.6
  Bottom Layer w0.102: U2.12 1.573,1.383 4.575,4.385 7.005,4.385 v2(7.404,4.784)
P1.0/QSPI: U2.34 U3.AD22 | length 5.3
  Top Layer w0.102: U3.AD22 15.248,8.284 15.603,8.639 v1@15.603,10.018 ; v1(15.593,10.008) v1@15.603,10.018 ; v1@15.603,10.018 15.609,10.024 15.609,10.034 15.603,10.028 v1@15.603,10.018
  Bottom Layer w0.102: v1(15.593,10.008) 16.151,10.566 U2.34
P1.10: U2.1 U3.A20 | length 9.6
  Bottom Layer w0.102: -0.129,12.766 U2.1 2.414,12.766 7.4,7.78 v2(7.404,7.784)
P1.11: U2.2 U3.B19 | length 9.7
  Bottom Layer w0.102: U2.2 2.918,11.666 7.126,7.458 7.761,7.458 7.837,7.534 v2(7.904,7.534)
P1.12: U2.3 U3.B17 | length 9.3
  Bottom Layer w0.102: U2.3 3.487,10.566 6.831,7.222 7.716,7.222 v2(7.904,7.034)
P1.13: U2.4 U3.A16 | length 8.5
  Bottom Layer w0.102: U2.4 4.092,9.466 6.586,6.972 7.216,6.972 v2(7.404,6.784)
P1.14: U2.5 U3.B15 | length 8.7
  Bottom Layer w0.102: U2.5 4.707,8.366 6.324,6.749 6.91,6.749 7.201,6.458 7.828,6.458 v2(7.904,6.534)
P1.15: U2.6 U3.A14 | length 7.8
  Top Layer w0.102: v1(6.859,6.268) 7.388,6.268 U3.A14
  Bottom Layer w0.102: 0.022,7.266 5.328,7.266 6.326,6.268 v1(6.859,6.268)
RXEN: R4.1 U3.U1 | length 10.8
  Top Layer w0.102: v3(15.14,10.885) 15.164,10.909 R4.1
  Bottom Layer w0.102: v2(11.904,2.785) 12.957,3.838 12.957,10.092 14.034,11.169 14.852,11.169 v3@15.132,10.889
SWDCLK: U2.36 U3.AA24 | length 7.2
  Top Layer w0.102: U3.AA24 12.904,9.807 13.222,10.125 14.237,10.125 14.774,10.662 v1(14.774,11.583)
  Bottom Layer w0.102: v1(14.774,11.583) 15.321,11.583 15.545,11.807 15.545,12.514 15.728,12.697 17.353,12.697 U2.36
SWDIO: U2.35 U3.AC24 | length 5.4
  Top Layer w0.102: U3.AC24 13.908,9.284 15.027,10.403 15.77,10.403 16.009,10.642 v1(16.009,10.919)
  Bottom Layer w0.102: v1(16.009,10.919) 16.009,11.261 16.368,11.62 17.377,11.62 U2.35 17.39,11.698
TXEN: R3.1 U3.T2 | length 11.3
  Top Layer w0.203: v3@15.101,12.087 15.675,12.087 R3.1
  Bottom Layer w0.102: v2(11.652,3.283) 12.67,4.301 12.67,10.372 14.373,12.075 15.089,12.075 v3(15.101,12.087) ; v3@15.084,12.087 v3@15.124,12.127
VCC_3.0V: C1.1 C16.1 C18.1 C19.1 C22.1 C23.1 IC1.14 L4.1 R5.1 U2.24 U2.25 U3.A22 U3.AD14 U3.AD23 U3.B1 U3.W1 U3.Y2 | length 27.6
  Top Layer w0.102: C19.1 6.626,2.743 6.404,2.521 5.173,2.521 4.974,2.322 4.974,1.339 5.158,1.155 9.828,1.155 10.482,1.809 12.247,1.809 C18.1
  Top Layer w0.203: C16.1 6.35,8.034 6.398,8.082 6.423,8.082 6.625,8.284 v2(7.404,8.284) ; C19.1 6.692,2.784 U3.B1 ; C1.1 10.571,13.751 v1@11.086,13.751 ; v1@11.151,13.68 IC1.14 ; C18.1@12.398,1.933 12.401,1.936 12.401,2.781 U3.W1 ; U3.Y2 12.654,3.258 12.423,3.026 12.423,2.803 U3.W1 ; U3.AD14 13.914,6.274 14.901,6.274 C22.1 14.923,6.252 15.276,6.252 v3(15.288,6.24) ; U3.AD23 13.911,8.777 14.888,8.777 C23.1@14.894,8.771 ; C23.1 14.864,8.814 15.229,8.814 v3(15.248,8.833) ; L4.1@15.015,2.196 14.635,2.576 13.333,2.576 13.125,2.784 U3.W1 ; R5.1 15.749,13.846 v2(15.749,14.25) v1(15.749,14.898)
  Top Layer w0.35: v1(14.905,1.422) 14.905,1.955 15.08,2.13 L4.1
  Bottom Layer w0.203: v3(15.248,8.833) 15.445,9.03 v3(16.032,9.03) ; 15.305,0.554 15.371,0.488
  Bottom Layer w0.35: U2.24 14.773,0.355 14.905,0.488 ; 14.871,0.488 14.905,0.488 ; v1(14.905,1.422) 14.905,0.488 ; U2.25 15.971,0.135 15.971,0.488 15.371,0.488 14.905,0.488
  other v1: 11.024,13.752
  other v2: 15.305,1.42 15.68,1.422
XC1: C9.1 U3.B24 Y1.1 | length 6.4
  Top Layer w0.102: C9.1 3.91,11.005 3.898,10.993 4.649,10.242 5.763,10.242 6.721,9.284 U3.B24
XC2: C8.1 U3.A23 Y1.3 | length 5
  Top Layer w0.102: C8.1 4.888,7.855 5.198,8.164 Y1.3 5.621,8.972 7.216,8.972 U3.A23
pads on no net: C10.2 IC1.1 IC1.7 IC1.12 IC1.13 IC1.15 IC1.16 U2.@0.022,1.766 U2.@0.022,2.866 U2.@0.022,3.966 U2.@0.022,5.066 U2.@0.022,6.166 U2.@0.022,7.266 U2.@0.022,8.366 U2.@0.022,9.466 U2.@0.022,10.566 U2.@0.022,11.666 U2.@0.023,12.766 U2.@1.573,0.036 U2.@2.673,0.036 U2.@3.773,0.036 U2.@4.873,0.036 U2.@5.973,0.036 U2.@7.073,0.036 U2.@8.173,0.036 U2.@9.273,0.036 U2.@10.373,0.036 U2.@11.473,0.036 U2.@12.573,0.036 U2.@13.672,0.036 U2.@14.772,0.036 U2.@15.872,0.036 U2.@17.423,2.866 U2.@17.423,6.166 U2.@17.423,8.366 U2.@17.423,9.466 U2.@17.423,10.566 U2.@17.423,11.666 U2.@17.423,12.766 U3.AC5 U3.AC9 U3.AC11 U3.AD2 U3.AD4 U3.AD6 U3.AD8 U3.AD10 U3.AD12 U3.J24 U3.L24 U3.P2 U3.P23 U3.R1 U3.R24 U3.T23 U3.U24 U3.V23 U3.W24 U3.Y23

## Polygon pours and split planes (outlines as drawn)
GND on Top Layer "Top Layer-GND" (solid, remove dead copper, pour order 2): 0.707,19.211 0.707,0.616 17.195,0.616 16.786,1.024 16.786,19.211
no net on Top Layer "Top Layer-No Net" (solid, remove dead copper, pour order 0): 9.032,14.285
GND on Bottom Layer "Bottom_GND" (solid, remove dead copper, pour order 20): 12.036,15.299 16.741,15.299 16.787,15.345 16.787,19.212 12.036,19.211
GND on Bottom Layer "Bottom Layer-No Net 2" (solid, remove dead copper, pour order 18): 12.654,14.281 12.654,12.579 14.356,12.579 14.354,12.581 14.354,14.28
GND on Bottom Layer "Bottom_GND" (solid, remove dead copper, pour order 16): 0.694,19.211 0.694,0.576 14.096,0.576 14.097,2.135 14.097,2.66 6.628,2.66 6.628,9.691 11.794,9.691 12.13,10.027 12.13,19.211
GND on Bottom Layer "Bottom Layer-GND" (solid, remove dead copper, pour order 14): 13.374,0.361 13.372,1.609 13.888,2.125 17.011,2.125 17.011,0.475 16.879,0.343
GND on Bottom Layer "Bottom Layer-GND 1" (solid, remove dead copper, pour order 10): 8.179,3.559 13.205,3.559 13.205,8.505 8.246,8.505
no net on Bottom Layer "Bottom Layer-No Net" (solid, remove dead copper, pour order 8): 1.126,1.185
no net on Bottom Layer "Bottom Layer-No Net 1" (solid, remove dead copper, pour order 6): 0.681,0.683
GND on Layer 3 "Layer 3-GND" (solid, remove dead copper, pour order 30): 0.732,19.207 16.786,19.207 16.786,15.381 0.732,15.381
VCC_3.0V on Layer 3 "Layer 3-VCC_3.0V" (solid, remove dead copper, pour order 28): 0.738,14.43 0.738,0.731 16.784,0.731 16.787,14.472
GND on L2_GND "M1_GND" (solid, remove dead copper, pour order 26): 0.734,19.211 0.734,0.616 16.785,0.616 16.785,19.211

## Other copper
Top Layer:
  pour cut-out: 6.066,6.491 6.091,6.466 6.091,6.32 6.262,6.491
  pour cut-out: 13.228,8.458 13.078,8.608 13.113,8.643 13.113,8.784
  pour cut-out: 13.228,8.458
  pour cut-out: 3.09,10.185
  pour cut-out: 11.324,12.051 11.303,13.271 11.437,13.271
  pour cut-out: 11.437,12.253
  pour cut-out: 16.787,1.023 16.787,0.578 17.06,0.578 17.112,0.63 17.112,0.698
  pour cut-out: 12.405,3.559 11.981,3.559 11.981,3.307 12.405,3.307
  pour cut-out: 13.381,4.331 13.381,4.755 13.129,4.755 13.129,4.331
  pour cut-out: 9.86,8.507 10.932,8.507 10.932,8.994 9.86,8.994
  pour cut-out: 7.69,8.952 7.69,7.88 8.177,7.88 8.177,8.952
  pour cut-out: 9.024,10.082 8.041,10.081 8.041,12.051 11.425,12.051 11.425,10.073 9.033,10.073
Layer 3:
  region net GND: 12.654,14.281 12.655,14.28 14.354,14.28 14.354,12.581 14.356,12.579 12.654,12.579
  region net GND: 8.574,8.396 12.34,8.396 12.34,4.06 8.574,4.06
Bottom Layer:
  pour cut-out: 6.628,9.691 6.627,9.692 5.992,9.692 6.243,9.441 6.256,9.454 6.628,9.454

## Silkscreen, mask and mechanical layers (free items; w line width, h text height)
Top Overlay:
  circle w0.254: c12.318,11.612 r0.054
  lines w0.254: 12.56,16.364 ccw(c12.56,16.244) 12.576,16.363
Bottom Overlay:
  text "Meshtek-MTHP52-V1.0" at 14.071,16.68 h1
Top Solder:
  region: 16.466,1.087 16.466,10.935 16.795,10.935 16.795,1.087
  region: 16.332,18.701 16.787,18.701 16.787,14.558 16.332,14.558
  region: 4.303,0.84 4.303,1.108 4.572,0.84
  region: 10.392,0.843 10.66,1.111 16.794,1.111 16.794,0.844
  region: 0.679,1.108 0.679,2.631 1.321,2.631 1.321,1.108
  region: 0.679,1.108 0.679,1.21 1.23,1.21 1.23,1.108
  region: 0.679,2.631 0.679,8.255 1.321,8.255 1.321,2.631
  region: 0.679,8.251 0.679,14.381 1.321,14.381 1.321,8.251
  region: 0.679,0.571 0.679,1.108 4.303,1.108 4.303,0.571
  region: 0.679,0.571 0.679,0.844 16.794,0.844 16.794,0.571
  region: 1.32,13.852 1.32,14.382 5.038,14.382 5.038,13.852
  region: 4.295,14.68 4.296,15.536 5.038,15.536 5.038,14.381 4.295,14.381
  region: 16.787,19.211 4.207,19.211 4.207,18.697 16.787,18.697
  region: 4.207,18.697 4.207,17.613 4.887,17.613 4.887,18.697
Mechanical 1:
  lines w0.05: 0.012,20.794 0.013,20.594 ; 1.013,20.361 0.012,20.694 ; 1.012,21.028 0.012,20.694 ; 3.42,20.696 0.012,20.694 ; 14.063,20.702 17.47,20.704 ; 16.47,21.037 17.47,20.704 ; 16.471,20.37 17.47,20.704 ; 17.471,20.604 17.47,20.804 ; 18.943,18.448 19.275,19.449 ; 18.972,0.991 19.307,-0.008 ; 19.175,19.449 19.375,19.449 ; 19.207,-0.008 19.407,-0.008 ; 19.282,15.042 19.275,19.449 ; 19.3,4.399 19.307,-0.008 ; 19.61,18.45 19.275,19.449 ; 19.639,0.993 19.307,-0.008
  text "17.458 (mm)" at 3.674,20.044 h1 r0.03
  text "19.457 (mm)" at 18.63,14.787 h1 r270.09
Board Outline:
  the board outline again, w0.1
